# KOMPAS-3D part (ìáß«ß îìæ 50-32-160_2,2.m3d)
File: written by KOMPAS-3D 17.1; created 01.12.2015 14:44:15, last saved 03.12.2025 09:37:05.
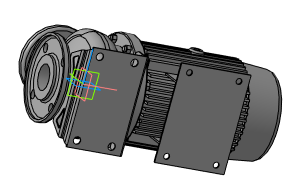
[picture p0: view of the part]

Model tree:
1. Операция без истории:6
